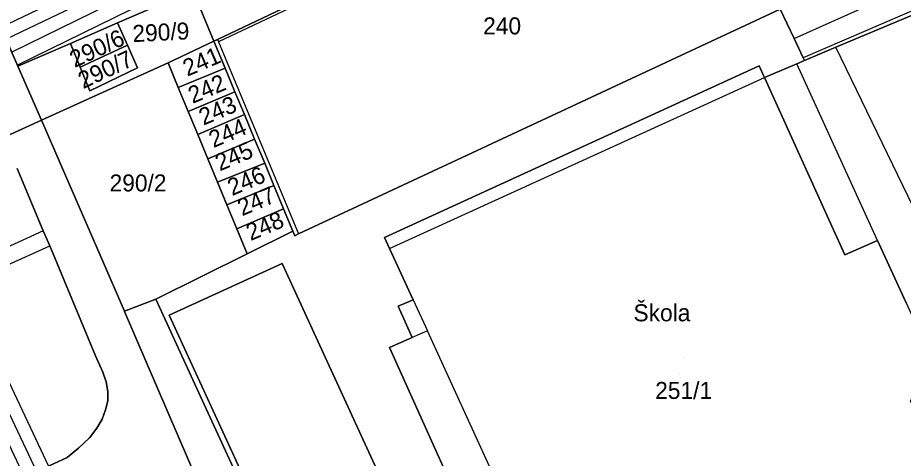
# Model space of a CAD drawing. Extents: x -264070 to -262271, y -1238894 to -1238141.
# Drawn here: x -263503.5 to -263399.4, y -1238573.9 to -1238522.1 of the extents above; entities that cross this region are included whole.
import ezdxf

# ---------------------------------------------------------------- set-up
doc = ezdxf.new("R2010")
doc.units = 0
for name, color, linetype in [('body_kn', 7, 'Continuous'), ('kladpar_druhypozemkov', 7, 'Continuous'), ('kladpar_hranice', 7, 'Continuous'), ('kladpar_parcelnecisla', 7, 'Continuous'), ('kladpar_plochy', 7, 'Continuous'), ('popisy', 7, 'Continuous'), ('tarchy_linie', 7, 'Continuous'), ('zappar_hrandruhpozemk', 7, 'Continuous'), ('znacky', 7, 'Continuous')]:
    doc.layers.add(name, color=color, linetype=linetype)

msp = doc.modelspace()

# ---------------------------------------------------------------- linework, layer by layer
at = {"layer": 'body_kn'}
for p, q in [((-263491.8, -1238522.76), (-263491.8, -1238522.76)), ((-263491.8, -1238522.76), (-263491.8, -1238522.76)), ((-263497.35, -1238525.17), (-263497.35, -1238525.17)), ((-263490.65, -1238525.35), (-263490.65, -1238525.35)), ((-263490.65, -1238525.35), (-263490.65, -1238525.35)), ((-263480.47, -1238524.91), (-263480.47, -1238524.91)), ((-263480.47, -1238524.91), (-263480.47, -1238524.91)), ((-263480.04, -1238524.71), (-263480.04, -1238524.71)), ((-263480.04, -1238524.71), (-263480.04, -1238524.71)), ((-263479.93, -1238524.97), (-263479.93, -1238524.97)), ((-263479.93, -1238524.97), (-263479.93, -1238524.97)), ((-263412.28, -1238524.59), (-263412.28, -1238524.59)), ((-263412.28, -1238524.59), (-263412.28, -1238524.59)), ((-263407.37, -1238525.62), (-263407.37, -1238525.62)), ((-263485.85, -1238527.44), (-263485.85, -1238527.44)), ((-263485.85, -1238527.44), (-263485.85, -1238527.44)), ((-263411.21, -1238526.84), (-263411.21, -1238526.84)), ((-263411.05, -1238527.18), (-263411.05, -1238527.18)), ((-263503.51, -1238527.84), (-263503.51, -1238527.84)), ((-263496.21, -1238527.97), (-263496.21, -1238527.97)), ((-263489.47, -1238528.04), (-263489.47, -1238528.04)), ((-263479.16, -1238528.07), (-263479.16, -1238528.07)), ((-263479.16, -1238528.07), (-263479.16, -1238528.07)), ((-263416.38, -1238527.81), (-263416.38, -1238527.81)), ((-263411.96, -1238527.56), (-263411.96, -1238527.56)), ((-263415.91, -1238528.86), (-263415.91, -1238528.86)), ((-263415.77, -1238529.17), (-263415.77, -1238529.17)), ((-263415.77, -1238529.17), (-263415.77, -1238529.17)), ((-263484.66, -1238530.33), (-263484.66, -1238530.33)), ((-263495.08, -1238530.75), (-263495.08, -1238530.75)), ((-263494.78, -1238531.48), (-263494.78, -1238531.48)), ((-263478, -1238530.86), (-263478, -1238530.86)), ((-263478, -1238530.86), (-263478, -1238530.86)), ((-263483.49, -1238533.16), (-263483.49, -1238533.16)), ((-263476.9, -1238533.52), (-263476.9, -1238533.52)), ((-263476.9, -1238533.52), (-263476.9, -1238533.52)), ((-263500.76, -1238534.18), (-263500.76, -1238534.18)), ((-263482.38, -1238535.86), (-263482.38, -1238535.86)), ((-263475.69, -1238536.41), (-263475.69, -1238536.41)), ((-263475.69, -1238536.41), (-263475.69, -1238536.41)), ((-263481.19, -1238538.73), (-263481.19, -1238538.73)), ((-263474.51, -1238539.26), (-263474.51, -1238539.26)), ((-263474.51, -1238539.26), (-263474.51, -1238539.26)), ((-263480.06, -1238541.48), (-263480.06, -1238541.48)), ((-263473.44, -1238541.86), (-263473.44, -1238541.86)), ((-263473.44, -1238541.86), (-263473.44, -1238541.86)), ((-263478.96, -1238544.13), (-263478.96, -1238544.13)), ((-263472.3, -1238544.63), (-263472.3, -1238544.63)), ((-263472.3, -1238544.63), (-263472.3, -1238544.63)), ((-263500.53, -1238547.19), (-263500.53, -1238547.19)), ((-263500.53, -1238547.19), (-263500.53, -1238547.19)), ((-263477.8, -1238546.96), (-263477.8, -1238546.96)), ((-263471.2, -1238547.26), (-263471.2, -1238547.26)), ((-263470.98, -1238547.79), (-263470.98, -1238547.79)), ((-263470.53, -1238547.57), (-263470.53, -1238547.57)), ((-263460.42, -1238547.97), (-263460.42, -1238547.97)), ((-263402.47, -1238548.32), (-263402.47, -1238548.32)), ((-263402.47, -1238548.32), (-263402.47, -1238548.32)), ((-263499.77, -1238548.96), (-263499.77, -1238548.96)), ((-263459.83, -1238549.28), (-263459.83, -1238549.28)), ((-263459.83, -1238549.28), (-263459.83, -1238549.28)), ((-263476.57, -1238549.91), (-263476.57, -1238549.91)), ((-263406.33, -1238550.04), (-263406.33, -1238550.04)), ((-263472.47, -1238551.04), (-263472.47, -1238551.04)), ((-263487.31, -1238555.22), (-263487.31, -1238555.22)), ((-263487.31, -1238555.22), (-263487.31, -1238555.22)), ((-263457.05, -1238555.33), (-263457.05, -1238555.33)), ((-263457.05, -1238555.33), (-263457.05, -1238555.33)), ((-263491, -1238556.66), (-263491, -1238556.66)), ((-263491, -1238556.66), (-263491, -1238556.66)), ((-263458.83, -1238556.06), (-263458.83, -1238556.06)), ((-263490.98, -1238556.7), (-263490.98, -1238556.7)), ((-263485.72, -1238557.13), (-263485.72, -1238557.13)), ((-263457.19, -1238559.75), (-263457.19, -1238559.75)), ((-263455.39, -1238558.95), (-263455.39, -1238558.95)), ((-263455.39, -1238558.95), (-263455.39, -1238558.95)), ((-263459.84, -1238560.91), (-263459.84, -1238560.91)), ((-263494.41, -1238561.92), (-263494.41, -1238561.92)), ((-263493.53, -1238563.82), (-263493.53, -1238563.82)), ((-263493.15, -1238564.97), (-263493.15, -1238564.97)), ((-263492.96, -1238566.11), (-263492.96, -1238566.11)), ((-263492.96, -1238567.19), (-263492.96, -1238567.19)), ((-263493.22, -1238568.27), (-263493.22, -1238568.27)), ((-263481.37, -1238568.14), (-263481.37, -1238568.14)), ((-263493.6, -1238569.35), (-263493.6, -1238569.35)), ((-263494.24, -1238570.42), (-263494.24, -1238570.42)), ((-263495.12, -1238571.56), (-263495.12, -1238571.56)), ((-263496.39, -1238572.77), (-263496.39, -1238572.77)), ((-263497.73, -1238573.84), (-263497.73, -1238573.84))]:
    msp.add_line(p, q, dxfattribs=at)
at = {"layer": 'kladpar_druhypozemkov'}
for p, q in [((-263485.9, -1238523.16), (-263485.9, -1238523.16)), ((-263494.09, -1238525.12), (-263494.09, -1238525.12)), ((-263482.85, -1238526.71), (-263482.85, -1238526.71)), ((-263492.79, -1238527.71), (-263492.79, -1238527.71)), ((-263481.73, -1238529.67), (-263481.73, -1238529.67)), ((-263480.45, -1238532.47), (-263480.45, -1238532.47)), ((-263479.29, -1238535.27), (-263479.29, -1238535.27)), ((-263478.41, -1238538.23), (-263478.41, -1238538.23)), ((-263489.4, -1238540.17), (-263489.4, -1238540.17)), ((-263477.37, -1238540.83), (-263477.37, -1238540.83)), ((-263475.93, -1238543.35), (-263475.93, -1238543.35)), ((-263474.85, -1238546.31), (-263474.85, -1238546.31)), ((-263425.75, -1238563.92), (-263425.75, -1238563.92))]:
    msp.add_line(p, q, dxfattribs=at)
at = {"layer": 'kladpar_hranice'}
for points in [[(-263423.02, -1238501.67), (-263410.31, -1238495.37), (-263411.57, -1238492.61), (-263411.74, -1238492.26), (-263405.83, -1238489.45), (-263392.22, -1238519.21), (-263407.37, -1238525.62), (-263411.05, -1238527.18), (-263411.21, -1238526.84), (-263412.28, -1238524.59), (-263413.92, -1238521.14), (-263423.02, -1238501.67)], [(-263411.74, -1238492.26), (-263480.04, -1238524.71), (-263480.47, -1238524.91), (-263482.95, -1238518.92), (-263491.8, -1238522.76), (-263497.35, -1238525.17), (-263503.51, -1238527.84), (-263505.24, -1238523.86), (-263507.42, -1238518.77)], [(-263411.74, -1238492.26), (-263411.57, -1238492.61), (-263410.31, -1238495.37), (-263423.02, -1238501.67), (-263413.92, -1238521.14), (-263470.53, -1238547.57), (-263470.98, -1238547.79), (-263471.2, -1238547.26), (-263472.3, -1238544.63), (-263473.44, -1238541.86), (-263474.51, -1238539.26), (-263475.69, -1238536.41), (-263476.9, -1238533.52), (-263478, -1238530.86), (-263479.16, -1238528.07), (-263480.47, -1238524.91), (-263480.04, -1238524.71), (-263411.74, -1238492.26)], [(-263507.42, -1238518.77), (-263505.24, -1238523.86), (-263503.51, -1238527.84), (-263500.76, -1238534.18), (-263506.27, -1238536.71), (-263507.17, -1238536.13), (-263508.5, -1238535.37), (-263510.02, -1238534.67), (-263511.22, -1238534.41), (-263512.23, -1238534.35), (-263513.5, -1238534.48), (-263516.2, -1238528.48), (-263518.17, -1238524.44), (-263521.92, -1238523.16), (-263521.21, -1238521.51)], [(-263485.85, -1238527.44), (-263494.78, -1238531.48), (-263500.76, -1238534.18), (-263503.51, -1238527.84), (-263497.35, -1238525.17), (-263496.21, -1238527.97), (-263495.08, -1238530.75), (-263489.47, -1238528.04), (-263490.65, -1238525.35), (-263491.8, -1238522.76), (-263482.95, -1238518.92), (-263480.47, -1238524.91), (-263485.85, -1238527.44)], [(-263399.12, -1238555.65), (-263402.47, -1238548.32), (-263406.33, -1238550.04), (-263415.77, -1238529.17), (-263411.96, -1238527.56), (-263411.05, -1238527.18), (-263407.37, -1238525.62), (-263392.22, -1238519.21)], [(-263487.31, -1238555.22), (-263476.57, -1238549.91), (-263471.2, -1238547.26), (-263470.98, -1238547.79), (-263470.53, -1238547.57), (-263413.92, -1238521.14), (-263412.28, -1238524.59), (-263411.21, -1238526.84), (-263411.05, -1238527.18), (-263411.96, -1238527.56), (-263415.77, -1238529.17), (-263415.91, -1238528.86), (-263416.38, -1238527.81), (-263460.42, -1238547.97), (-263459.83, -1238549.28), (-263457.05, -1238555.33), (-263458.83, -1238556.06), (-263457.19, -1238559.75), (-263459.84, -1238560.91), (-263451.19, -1238580.16)], [(-263491.8, -1238522.76), (-263490.65, -1238525.35), (-263496.21, -1238527.97), (-263497.35, -1238525.17), (-263491.8, -1238522.76)], [(-263490.65, -1238525.35), (-263489.47, -1238528.04), (-263495.08, -1238530.75), (-263496.21, -1238527.97), (-263490.65, -1238525.35)], [(-263480.47, -1238524.91), (-263479.16, -1238528.07), (-263484.66, -1238530.33), (-263485.85, -1238527.44), (-263480.47, -1238524.91)], [(-263485.85, -1238527.44), (-263484.66, -1238530.33), (-263483.49, -1238533.16), (-263482.38, -1238535.86), (-263481.19, -1238538.73), (-263480.06, -1238541.48), (-263478.96, -1238544.13), (-263477.8, -1238546.96), (-263476.57, -1238549.91), (-263487.31, -1238555.22), (-263491, -1238556.66), (-263500.76, -1238534.18), (-263494.78, -1238531.48), (-263485.85, -1238527.44)], [(-263479.16, -1238528.07), (-263478, -1238530.86), (-263483.49, -1238533.16), (-263484.66, -1238530.33), (-263479.16, -1238528.07)], [(-263430.29, -1238614.92), (-263433.51, -1238607.82), (-263433.05, -1238607.61), (-263435.9, -1238601.4), (-263437.27, -1238598.43), (-263446.62, -1238578.06), (-263451.19, -1238580.16), (-263459.84, -1238560.91), (-263457.19, -1238559.75), (-263458.83, -1238556.06), (-263457.05, -1238555.33), (-263459.83, -1238549.28), (-263460.42, -1238547.97), (-263416.38, -1238527.81), (-263415.91, -1238528.86), (-263415.77, -1238529.17)], [(-263415.77, -1238529.17), (-263406.33, -1238550.04), (-263402.47, -1238548.32), (-263399.12, -1238555.65), (-263398.13, -1238557.82), (-263394.67, -1238565.38), (-263398.65, -1238567.15), (-263389.34, -1238587.86), (-263423.21, -1238603.17), (-263421.51, -1238606.92), (-263420.97, -1238606.68), (-263420.38, -1238607.97), (-263420.91, -1238608.26), (-263420.75, -1238608.61), (-263420, -1238610.28)], [(-263478, -1238530.86), (-263476.9, -1238533.52), (-263482.38, -1238535.86), (-263483.49, -1238533.16), (-263478, -1238530.86)], [(-263476.9, -1238533.52), (-263475.69, -1238536.41), (-263481.19, -1238538.73), (-263482.38, -1238535.86), (-263476.9, -1238533.52)], [(-263506.27, -1238536.71), (-263500.76, -1238534.18), (-263491, -1238556.66), (-263490.98, -1238556.7), (-263470.95, -1238603.2), (-263447.72, -1238657.32), (-263439.61, -1238675.92), (-263432.36, -1238692.6), (-263431.35, -1238693.86)], [(-263475.69, -1238536.41), (-263474.51, -1238539.26), (-263480.06, -1238541.48), (-263481.19, -1238538.73), (-263475.69, -1238536.41)], [(-263503.62, -1238539.88), (-263500.53, -1238547.19), (-263499.77, -1238548.96), (-263494.41, -1238561.92), (-263493.53, -1238563.82), (-263493.15, -1238564.97), (-263492.96, -1238566.11), (-263492.96, -1238567.19), (-263493.22, -1238568.27), (-263493.6, -1238569.35), (-263494.24, -1238570.42), (-263495.12, -1238571.56), (-263496.39, -1238572.77), (-263497.73, -1238573.84), (-263514.63, -1238581.67)], [(-263514.63, -1238581.67), (-263497.73, -1238573.84), (-263496.39, -1238572.77), (-263495.12, -1238571.56), (-263494.24, -1238570.42), (-263493.6, -1238569.35), (-263493.22, -1238568.27), (-263492.96, -1238567.19), (-263492.96, -1238566.11), (-263493.15, -1238564.97), (-263493.53, -1238563.82), (-263494.41, -1238561.92), (-263499.77, -1238548.96), (-263500.53, -1238547.19), (-263503.62, -1238539.88)], [(-263474.51, -1238539.26), (-263473.44, -1238541.86), (-263478.96, -1238544.13), (-263480.06, -1238541.48), (-263474.51, -1238539.26)], [(-263473.44, -1238541.86), (-263472.3, -1238544.63), (-263477.8, -1238546.96), (-263478.96, -1238544.13), (-263473.44, -1238541.86)], [(-263472.3, -1238544.63), (-263471.2, -1238547.26), (-263476.57, -1238549.91), (-263477.8, -1238546.96), (-263472.3, -1238544.63)], [(-263458.49, -1238581.41), (-263472.47, -1238551.04), (-263485.72, -1238557.13), (-263462.31, -1238608.07)], [(-263433.5, -1238655.14), (-263436.64, -1238648.31), (-263442.57, -1238651.04), (-263453.28, -1238627.72), (-263456.9, -1238629.38), (-263465.85, -1238609.69), (-263462.89, -1238608.33), (-263462.31, -1238608.07), (-263485.72, -1238557.13), (-263472.47, -1238551.04), (-263458.49, -1238581.41), (-263455.97, -1238580.21), (-263452.76, -1238587.01), (-263454.31, -1238587.67), (-263456.41, -1238583.32), (-263457.4, -1238583.79), (-263448.33, -1238603.49), (-263446.96, -1238606.47), (-263430.66, -1238641.88), (-263429.6, -1238641.39), (-263431.76, -1238636.72), (-263430.57, -1238636.18), (-263427.76, -1238642.26)], [(-263491, -1238556.66), (-263487.31, -1238555.22), (-263481.37, -1238568.14), (-263462.89, -1238608.33), (-263465.85, -1238609.69), (-263456.9, -1238629.38), (-263453.28, -1238627.72), (-263442.57, -1238651.04), (-263436.64, -1238648.31), (-263433.5, -1238655.14)], [(-263462.89, -1238608.33), (-263481.37, -1238568.14), (-263487.31, -1238555.22)], [(-263447.72, -1238657.32), (-263470.95, -1238603.2), (-263490.98, -1238556.7), (-263491, -1238556.66)]]:
    msp.add_lwpolyline(points, dxfattribs=at)
at = {"layer": 'kladpar_plochy'}
for p, q in [((-263506.27, -1238536.71), (-263500.76, -1238534.18)), ((-263500.76, -1238534.18), (-263491, -1238556.66)), ((-263500.53, -1238547.19), (-263503.62, -1238539.88)), ((-263499.77, -1238548.96), (-263500.53, -1238547.19)), ((-263494.41, -1238561.92), (-263499.77, -1238548.96)), ((-263491, -1238556.66), (-263490.98, -1238556.7)), ((-263490.98, -1238556.7), (-263470.95, -1238603.2)), ((-263493.53, -1238563.82), (-263494.41, -1238561.92)), ((-263493.15, -1238564.97), (-263493.53, -1238563.82)), ((-263492.96, -1238566.11), (-263493.15, -1238564.97)), ((-263492.96, -1238567.19), (-263492.96, -1238566.11)), ((-263493.22, -1238568.27), (-263492.96, -1238567.19)), ((-263493.6, -1238569.35), (-263493.22, -1238568.27)), ((-263494.24, -1238570.42), (-263493.6, -1238569.35)), ((-263495.12, -1238571.56), (-263494.24, -1238570.42)), ((-263496.39, -1238572.77), (-263495.12, -1238571.56)), ((-263497.73, -1238573.84), (-263496.39, -1238572.77)), ((-263514.63, -1238581.67), (-263497.73, -1238573.84))]:
    msp.add_line(p, q, dxfattribs=at)
for points in [[(-263423.02, -1238501.67), (-263410.31, -1238495.37), (-263411.57, -1238492.61), (-263411.74, -1238492.26), (-263405.83, -1238489.45), (-263392.22, -1238519.21), (-263407.37, -1238525.62), (-263411.05, -1238527.18), (-263411.21, -1238526.84), (-263412.28, -1238524.59), (-263413.92, -1238521.14)], [(-263411.74, -1238492.26), (-263411.57, -1238492.61), (-263410.31, -1238495.37), (-263423.02, -1238501.67), (-263413.92, -1238521.14), (-263470.53, -1238547.57), (-263470.98, -1238547.79), (-263471.2, -1238547.26), (-263472.3, -1238544.63), (-263473.44, -1238541.86), (-263474.51, -1238539.26), (-263475.69, -1238536.41), (-263476.9, -1238533.52), (-263478, -1238530.86), (-263479.16, -1238528.07), (-263480.47, -1238524.91), (-263480.04, -1238524.71)], [(-263485.85, -1238527.44), (-263494.78, -1238531.48), (-263500.76, -1238534.18), (-263503.51, -1238527.84), (-263497.35, -1238525.17), (-263496.21, -1238527.97), (-263495.08, -1238530.75), (-263489.47, -1238528.04), (-263490.65, -1238525.35), (-263491.8, -1238522.76), (-263482.95, -1238518.92), (-263480.47, -1238524.91)], [(-263491.8, -1238522.76), (-263490.65, -1238525.35), (-263496.21, -1238527.97), (-263497.35, -1238525.17)], [(-263490.65, -1238525.35), (-263489.47, -1238528.04), (-263495.08, -1238530.75), (-263496.21, -1238527.97)], [(-263480.47, -1238524.91), (-263479.16, -1238528.07), (-263484.66, -1238530.33), (-263485.85, -1238527.44)], [(-263485.85, -1238527.44), (-263484.66, -1238530.33), (-263483.49, -1238533.16), (-263482.38, -1238535.86), (-263481.19, -1238538.73), (-263480.06, -1238541.48), (-263478.96, -1238544.13), (-263477.8, -1238546.96), (-263476.57, -1238549.91), (-263487.31, -1238555.22), (-263491, -1238556.66), (-263500.76, -1238534.18), (-263494.78, -1238531.48)], [(-263479.16, -1238528.07), (-263478, -1238530.86), (-263483.49, -1238533.16), (-263484.66, -1238530.33)], [(-263478, -1238530.86), (-263476.9, -1238533.52), (-263482.38, -1238535.86), (-263483.49, -1238533.16)], [(-263476.9, -1238533.52), (-263475.69, -1238536.41), (-263481.19, -1238538.73), (-263482.38, -1238535.86)], [(-263475.69, -1238536.41), (-263474.51, -1238539.26), (-263480.06, -1238541.48), (-263481.19, -1238538.73)], [(-263474.51, -1238539.26), (-263473.44, -1238541.86), (-263478.96, -1238544.13), (-263480.06, -1238541.48)], [(-263473.44, -1238541.86), (-263472.3, -1238544.63), (-263477.8, -1238546.96), (-263478.96, -1238544.13)], [(-263472.3, -1238544.63), (-263471.2, -1238547.26), (-263476.57, -1238549.91), (-263477.8, -1238546.96)]]:
    msp.add_lwpolyline(points, close=True, dxfattribs=at)
for points in [[(-263411.74, -1238492.26), (-263480.04, -1238524.71), (-263480.47, -1238524.91), (-263482.95, -1238518.92), (-263491.8, -1238522.76), (-263497.35, -1238525.17), (-263503.51, -1238527.84), (-263505.24, -1238523.86), (-263507.42, -1238518.77)], [(-263507.42, -1238518.77), (-263505.24, -1238523.86), (-263503.51, -1238527.84), (-263500.76, -1238534.18), (-263506.27, -1238536.71), (-263507.17, -1238536.13), (-263508.5, -1238535.37), (-263510.02, -1238534.67), (-263511.22, -1238534.41), (-263512.23, -1238534.35), (-263513.5, -1238534.48), (-263516.2, -1238528.48), (-263518.17, -1238524.44), (-263521.92, -1238523.16), (-263521.21, -1238521.51)], [(-263399.12, -1238555.65), (-263402.47, -1238548.32), (-263406.33, -1238550.04), (-263415.77, -1238529.17), (-263411.96, -1238527.56), (-263411.05, -1238527.18), (-263407.37, -1238525.62), (-263392.22, -1238519.21)], [(-263462.89, -1238608.33), (-263481.37, -1238568.14), (-263487.31, -1238555.22), (-263476.57, -1238549.91), (-263471.2, -1238547.26), (-263470.98, -1238547.79), (-263470.53, -1238547.57), (-263413.92, -1238521.14), (-263412.28, -1238524.59), (-263411.21, -1238526.84), (-263411.05, -1238527.18), (-263411.96, -1238527.56), (-263415.77, -1238529.17), (-263415.91, -1238528.86), (-263416.38, -1238527.81), (-263460.42, -1238547.97), (-263459.83, -1238549.28), (-263457.05, -1238555.33), (-263458.83, -1238556.06), (-263457.19, -1238559.75), (-263459.84, -1238560.91), (-263451.19, -1238580.16)], [(-263451.19, -1238580.16), (-263459.84, -1238560.91), (-263457.19, -1238559.75), (-263458.83, -1238556.06), (-263457.05, -1238555.33), (-263459.83, -1238549.28), (-263460.42, -1238547.97), (-263416.38, -1238527.81), (-263415.91, -1238528.86), (-263415.77, -1238529.17), (-263406.33, -1238550.04), (-263402.47, -1238548.32), (-263399.12, -1238555.65)], [(-263503.62, -1238539.88), (-263500.53, -1238547.19), (-263499.77, -1238548.96), (-263494.41, -1238561.92), (-263493.53, -1238563.82), (-263493.15, -1238564.97), (-263492.96, -1238566.11), (-263492.96, -1238567.19), (-263493.22, -1238568.27), (-263493.6, -1238569.35), (-263494.24, -1238570.42), (-263495.12, -1238571.56), (-263496.39, -1238572.77), (-263497.73, -1238573.84), (-263514.63, -1238581.67)], [(-263458.49, -1238581.41), (-263472.47, -1238551.04), (-263485.72, -1238557.13), (-263462.31, -1238608.07)], [(-263462.31, -1238608.07), (-263485.72, -1238557.13), (-263472.47, -1238551.04), (-263458.49, -1238581.41)], [(-263447.72, -1238657.32), (-263470.95, -1238603.2), (-263490.98, -1238556.7), (-263491, -1238556.66), (-263487.31, -1238555.22), (-263481.37, -1238568.14), (-263462.89, -1238608.33), (-263465.85, -1238609.69), (-263456.9, -1238629.38), (-263453.28, -1238627.72), (-263442.57, -1238651.04), (-263436.64, -1238648.31), (-263433.5, -1238655.14)]]:
    msp.add_lwpolyline(points, dxfattribs=at)
at = {"layer": 'tarchy_linie'}
for points in [[(-263505.5, -1238523.25), (-263412.72, -1238478.92), (-263415.25, -1238472.76), (-263405.35, -1238468.34), (-263404.7, -1238469.74), (-263404.05, -1238471.14), (-263411.27, -1238474.36), (-263408.76, -1238480.44), (-263431.07, -1238491.1), (-263430.66, -1238491.93), (-263471.25, -1238511.83), (-263503.57, -1238527.71), (-263504.22, -1238526.2), (-263504.89, -1238524.66), (-263505.5, -1238523.25)], [(-263404.7, -1238469.74), (-263413.26, -1238473.56), (-263410.74, -1238479.68), (-263504.89, -1238524.66)], [(-263432.73, -1238491.11), (-263471.98, -1238510.35), (-263504.22, -1238526.2)], [(-263510.77, -1238551.88), (-263499.93, -1238574.86), (-263501.34, -1238575.51), (-263502.75, -1238576.17), (-263512.27, -1238555.98)], [(-263651.39, -1238621.79), (-263634.28, -1238612.66), (-263633.98, -1238612.67), (-263633.77, -1238612.82), (-263624.03, -1238608.06), (-263624.37, -1238607.36), (-263623.97, -1238607.16), (-263609.63, -1238599.24), (-263559.99, -1238575.98), (-263511.52, -1238553.93), (-263501.34, -1238575.51)]]:
    msp.add_lwpolyline(points, dxfattribs=at)
at = {"layer": 'zappar_hrandruhpozemk'}
for p, q in [((-263411.57, -1238492.61), (-263479.93, -1238524.97)), ((-263412.28, -1238524.59), (-263399.77, -1238518.96)), ((-263392.82, -1238518.94), (-263411.21, -1238526.84)), ((-263480.04, -1238524.71), (-263479.93, -1238524.97)), ((-263479.93, -1238524.97), (-263470.53, -1238547.57)), ((-263396.04, -1238549.06), (-263407.37, -1238525.62)), ((-263402.47, -1238548.32), (-263411.96, -1238527.56)), ((-263459.83, -1238549.28), (-263415.77, -1238529.17)), ((-263500.53, -1238547.19), (-263521.43, -1238556.8)), ((-263556.1, -1238574.53), (-263499.77, -1238548.96)), ((-263457.05, -1238555.33), (-263455.39, -1238558.95)), ((-263455.39, -1238558.95), (-263457.19, -1238559.75)), ((-263446.62, -1238578.06), (-263455.39, -1238558.95))]:
    msp.add_line(p, q, dxfattribs=at)
at = {"layer": 'znacky'}
msp.add_line((-263425.14, -1238562.13), (-263425.14, -1238562.13), dxfattribs=at)

# ---------------------------------------------------------------- texts
at = {"layer": 'kladpar_parcelnecisla'}
for s, p in [('240', (-263448.83, -1238524.1)), ('290/2', (-263492.74, -1238542.57)), ('251/1', (-263428.61, -1238566.97))]:
    msp.add_text(s, height=2, dxfattribs=at).set_placement(p)
for s, rotation, p in [('290/9', 3, (-263490, -1238525.02)), ('290/6', 25, (-263496.84, -1238528.06)), ('290/7', 25, (-263495.85, -1238530.54)), ('241', 23, (-263483.6, -1238529.08)), ('242', 23, (-263482.98, -1238532.28)), ('243', 23, (-263481.71, -1238534.84)), ('244', 23, (-263480.54, -1238537.48)), ('245', 23, (-263479.79, -1238540.22)), ('246', 23, (-263478.34, -1238543.12)), ('247', 23, (-263477.17, -1238545.5)), ('248', 23, (-263476.16, -1238548.41))]:
    msp.add_text(s, height=2, rotation=rotation, dxfattribs=at).set_placement(p)
at = {"layer": 'popisy'}
msp.add_text('Škola', height=2, dxfattribs=at).set_placement((-263431.16, -1238557.84))

doc.saveas('drawing.dxf')
